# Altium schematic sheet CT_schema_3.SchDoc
size 362 x 192 mm
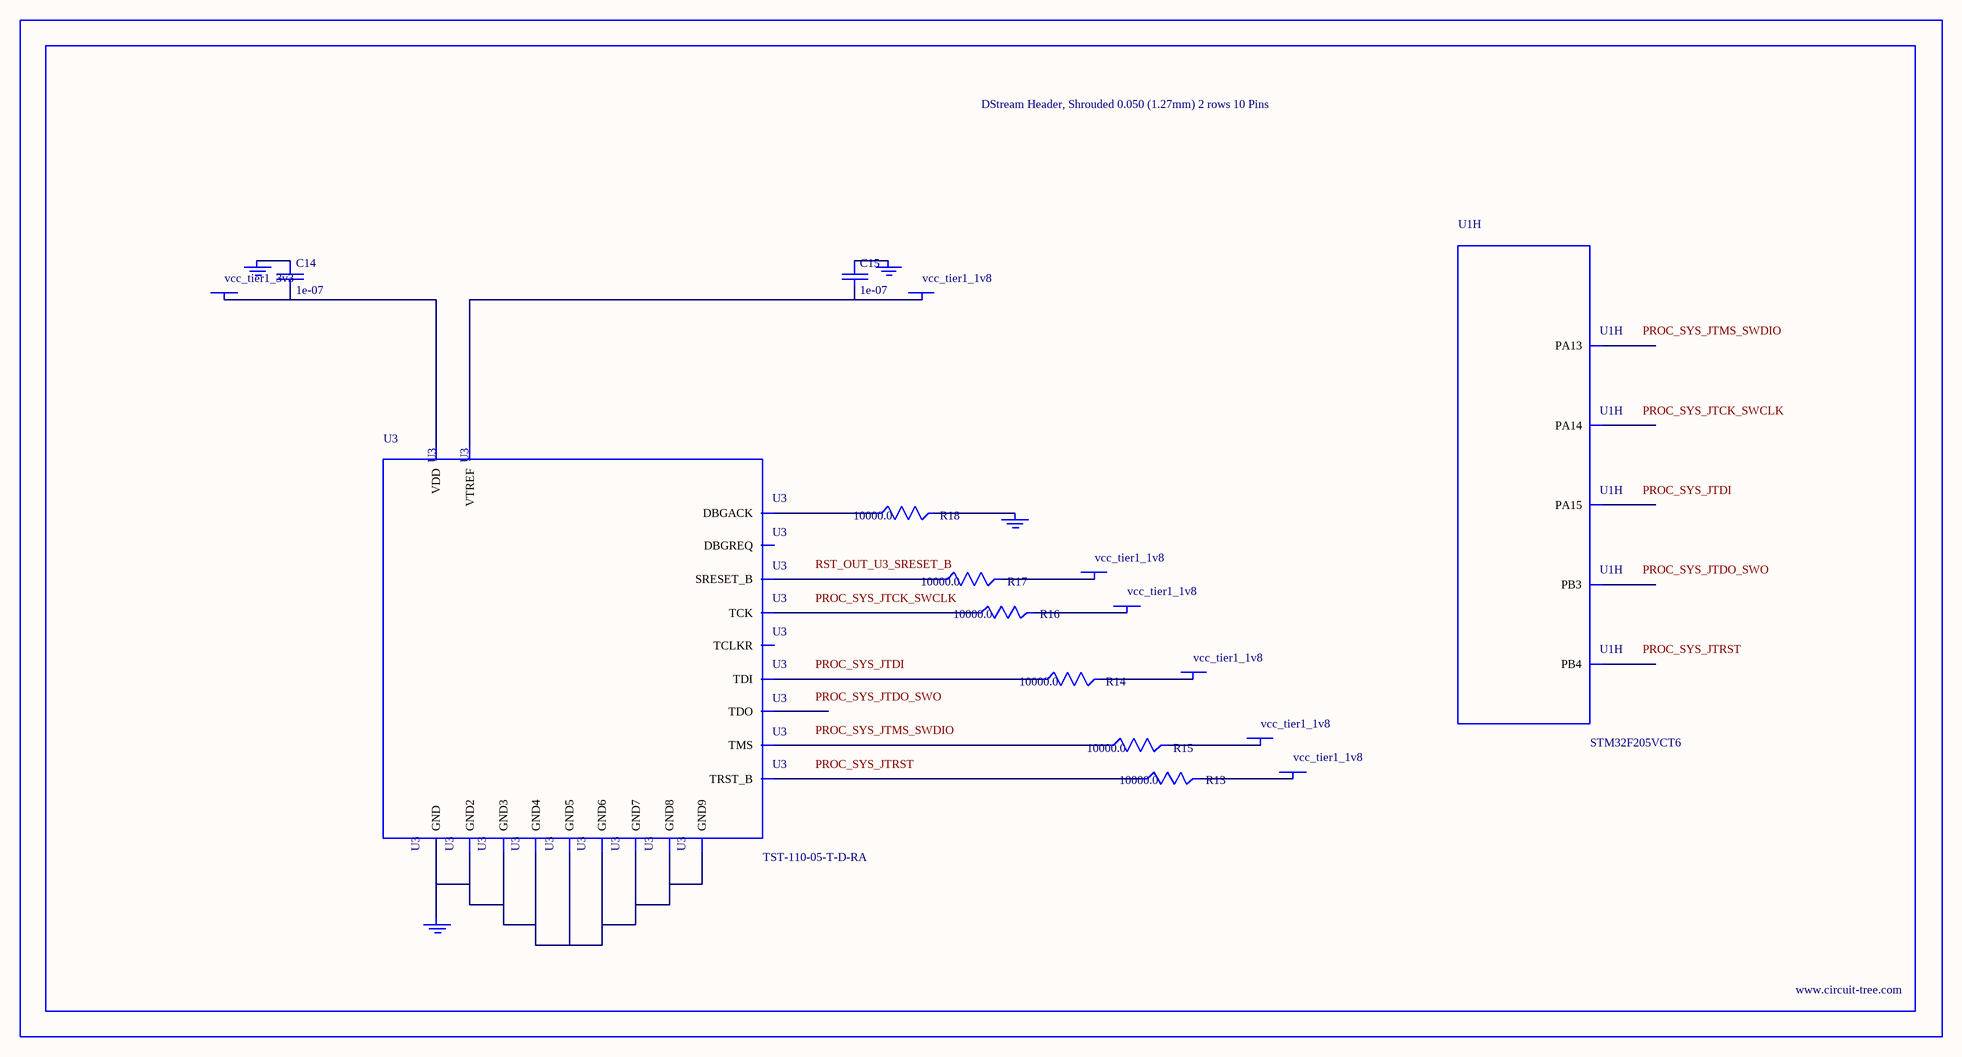
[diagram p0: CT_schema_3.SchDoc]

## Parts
BORDER2  (no value)
C14  1e-07  [C0402]
C15  1e-07  [C0402]
GND_INSTANCE_2_0  (no value)
GND_INSTANCE_2_1  (no value)
GND_INSTANCE_2_2  (no value)
GND_INSTANCE_2_3  (no value)
POWER_INSTANCE_2_0  vcc_tier1_1v8
POWER_INSTANCE_2_1  vcc_tier1_3v3
POWER_INSTANCE_2_2  vcc_tier1_1v8
POWER_INSTANCE_2_3  vcc_tier1_1v8
POWER_INSTANCE_2_4  vcc_tier1_1v8
POWER_INSTANCE_2_5  vcc_tier1_1v8
POWER_INSTANCE_2_6  vcc_tier1_1v8
R13  10000.0  [R0603]
R14  10000.0  [R0603]
R15  10000.0  [R0603]
R16  10000.0  [R0603]
R17  10000.0  [R0603]
R18  10000.0  [R0603]
U1  STM32F205VCT6  [LQFP100]  (part H of 10)
U3  TST-110-05-T-D-RA  [TST-110-05-T-D-RA]

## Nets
NetC14_1: C14.1 GND_INSTANCE_2_1.0(GND)
NetC14_2: C14.2 POWER_INSTANCE_2_1.0(PWR) U3.2(VDD)
NetC15_1: C15.1 GND_INSTANCE_2_0.0(GND)
NetC15_2: C15.2 POWER_INSTANCE_2_0.0(PWR) U3.1(VTREF)
NetGND_INSTANCE_2_2_0: GND_INSTANCE_2_2.0(GND) R18.2
NetGND_INSTANCE_2_3_0: GND_INSTANCE_2_3.0(GND) U3.4(GND) U3.6(GND2) U3.8(GND3) U3.10(GND4) U3.12(GND5) U3.14(GND6) U3.16(GND7) U3.18(GND8) U3.20(GND9)
NetPOWER_INSTANCE_2_2_0: POWER_INSTANCE_2_2.0(PWR) R13.2
NetPOWER_INSTANCE_2_3_0: POWER_INSTANCE_2_3.0(PWR) R14.2
NetPOWER_INSTANCE_2_4_0: POWER_INSTANCE_2_4.0(PWR) R15.2
NetPOWER_INSTANCE_2_5_0: POWER_INSTANCE_2_5.0(PWR) R16.2
NetPOWER_INSTANCE_2_6_0: POWER_INSTANCE_2_6.0(PWR) R17.2
NetR13_1: R13.1 U3.3(TRST_B)
NetR14_1: R14.1 U3.5(TDI)
NetR15_1: R15.1 U3.7(TMS)
NetR16_1: R16.1 U3.9(TCK)
NetR17_1: R17.1 U3.15(SRESET_B)
NetR18_1: R18.1 U3.19(DBGACK)

Not connected (* = marked no-connect by the designer): U1 72(PA13) 76(PA14) 77(PA15) 89(PB3) 90(PB4); U3 11(TCLKR) 13(TDO) 17(DBGREQ)

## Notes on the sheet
- Labels drawn without touching a wire or pin: PROC_SYS_JTCK_SWCLK, PROC_SYS_JTDI, PROC_SYS_JTDO_SWO, PROC_SYS_JTMS_SWDIO, PROC_SYS_JTRST, RST_OUT_U3_SRESET_B

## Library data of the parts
BORDER2 = BORDER_PAGE2
C14 C15 = C0402C104K3RACTU
GND_INSTANCE_2_0-GND_INSTANCE_2_3 = GND
POWER_INSTANCE_2_0-POWER_INSTANCE_2_6 = PWR
R13-R18 = RC0603JR-0710KL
